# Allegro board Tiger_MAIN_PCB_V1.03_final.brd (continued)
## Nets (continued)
ISH_GYRO2_IRQ*: R113.2 U1.BB7(GPP_A_20_ISH_GP_2)
ISOLATEB: R315.1 R316.1 U9.26(ISOLATEB)
ISW: R3091.2 U2529.10(ISW)
ITP_PMODE: R719.2 U1.E8(ITP_PMODE)
KBC_FAN_SPEED: C608.2 Q47.3(OUT) R607.2 U22.47(TACH0A/GPD6(3))
L_BKLT_EN: R454.1 R455.1 U1.R12(L_BKLTEN) U27.2(B)
L_BRIGHTNESS: Q76.1(G) R3111.1 R3123.2 U1.R11(L_BKLTCTL)
L_OUT+: CN21.2 R628.2
L_OUT-: CN21.1 R627.2
L_VDD_EN: R440.2 U1.U13(L_VDDEN) U25.3(EN/ENB)
LAN_CLK_REQ*: R1.2 U1.AT10(GPP_B_8_SRCCLKREQB_3) U9.16(CLKREQB)
LAN_CMT: R332.2 U11.21(MCT2)
LAN_CMT1: R334.2 U11.15(MCT4)
LAN_CT: R331.2 U11.24(MCT1)
LAN_CT1: R333.2 U11.18(MCT3)
LAN_N1: C399.1 C400.2 C401.2 C402.1 R331.1 R332.1 R333.1 R334.1
LAN_PCIE_CLK_DN: U1.D40(CLKOUT_SRC_N_3) U9.20(REFCLK_N)
LAN_PCIE_CLK_DP: U1.C40(CLKOUT_SRC_P_3) U9.19(REFCLK_P)
LAN_PLT_RST#: R317.1 U9.25(PERSTB) U10.4(Y)
LAN_RST: R318.2 U1.AD1(GPP_C_20_UART2_RXD)
LAN_TX0N: FIL1.1(UNB) R320.2 U11.22(MX1-)
LAN_TX0P: FIL1.4(GND) R319.2 U11.23(MX1+)
LAN_TX1N: FIL2.1(UNB) R324.2 U11.19(MX2-)
LAN_TX1P: FIL2.4(GND) R322.2 U11.20(MX2+)
LAN_TX2N: FIL3.4(GND) R329.2 U11.16(MX3-)
LAN_TX2P: FIL3.1(UNB) R327.2 U11.17(MX3+)
LAN_TX3N: FIL4.4(GND) R335.2 U11.13(MX4-)
LAN_TX3P: FIL4.1(UNB) R330.2 U11.14(MX4+)
LAN_VDDEN: R142.1 R309.2 U8.3(EN/ENB) U22.124(TMRI1/WUI3/GPC6(3))
LANWAKEB: R313.1 U9.28(LANWAKEB)
LAO1_CLKN: CN35.8 U2526.35(TCK1N)
LAO1_CLKP: CN35.9 U2526.34(TCK1P)
LAO1_DATAN0: CN35.24 U2526.42(TA1N)
LAO1_DATAN1: CN35.2 U2526.40(TB1N)
LAO1_DATAN2: CN35.5 U2526.37(TC1N)
LAO1_DATAN3: CN35.10 U2526.32(TD1N)
LAO1_DATAP0: CN35.23 U2526.41(TA1P)
LAO1_DATAP1: CN35.3 U2526.39(TB1P)
LAO1_DATAP2: CN35.6 U2526.36(TC1P)
LAO1_DATAP3: CN35.11 U2526.31(TD1P)
LAO_CLKN: CN35.30 U2526.47(TCK0N)
LAO_CLKP: CN35.29 U2526.46(TCK0P)
LAO_DATAN0: CN35.39 U2526.54(TA0N)
LAO_DATAN1: CN35.36 U2526.52(TB0N)
LAO_DATAN2: CN35.33 U2526.49(TC0N)
LAO_DATAN3: CN35.27 U2526.44(TD0N)
LAO_DATAP0: CN35.38 U2526.53(TA0P)
LAO_DATAP1: CN35.35 U2526.51(TB0P)
LAO_DATAP2: CN35.32 U2526.48(TC0P)
LAO_DATAP3: CN35.26 U2526.43(TD0P)
LCD_VCC: C491.1 C495.2 C942.2 CN35.13 CN35.14 CN35.15 U25.1(VOUT)
LDO2-CAP: C444.2 U16.39(LDO2-CAP)
LDR: R606.1 U2529.11(LDR)
LED_ON: R453.2 U22.19(L80HLAT/BAO/WUI24/GPE0)
LPC_CLKRUN*: R94.2 U1.AW11(GPP_A_8_CLKRUNB) U22.93(CLKRUN#/WUI16/ID0/GPH0)
LPC_FRAME*: CN16.9 U1.BA12(GPP_A_5_LFRAMEB_ESPI_CSB) U22.6(LFRAME#/GPM5(3))
LPC_LAD[0]: CN16.8 U1.AY13(GPP_A_1_LAD_0_ESPI_IO_0) U22.10(LAD0/GPM0(3))
LPC_LAD[1]: CN16.7 U1.BA13(GPP_A_2_LAD_1_ESPI_IO_1) U22.9(LAD1/GPM1(3))
LPC_LAD[2]: CN16.6 U1.BB13(GPP_A_3_LAD_2_ESPI_IO_2) U22.8(LAD2/GPM2(3))
LPC_LAD[3]: CN16.5 U1.AY12(GPP_A_4_LAD_3_ESPI_IO_3) U22.7(LAD3/GPM3(3))
LPCPD#: R488.2 U22.17(LPCPD#/WUI6/GPE6)
M_B_A0: CN1.144(A0) U1.BA46(DDR1_MA_0_CAB9)
M_B_A1: CN1.133(A1) U1.AY46(DDR1_MA_1_CAB8)
M_B_A2: CN1.132(A2) U1.AY47(DDR1_MA_2_CAB5)
M_B_A3: CN1.131(A3) U1.BB46(DDR1_MA_3)
M_B_A4: CN1.128(A4) U1.BA47(DDR1_MA_4)
M_B_A5: CN1.126(A5) U1.AY48(DDR1_MA_5_CAA0)
M_B_A6: CN1.127(A6) U1.BA48(DDR1_MA_6_CAA2)
M_B_A7: CN1.122(A7) U1.AP48(DDR1_MA_7_CAA4)
M_B_A8: CN1.125(A8) U1.BB48(DDR1_MA_8_CAA3)
M_B_A9: CN1.121(A9) U1.AP50(DDR1_MA_9_CAA1)
M_B_A10: CN1.146(A10_AP) U1.AW46(DDR1_MA_10_CAB7)
M_B_A11: CN1.120(A11) U1.AN48(DDR1_MA_11_CAA7)
M_B_A12: CN1.119(A12) U1.AN50(DDR1_MA_12_CAA6)
M_B_A13: CN1.158(A13) U1.BA43(DDR1_MA_13_CAB0)
M_B_ACT_N: CN1.114(ACT*) U1.AN53(DDR1_MA_15_CAA8_ACT_N)
M_B_BG0: CN1.115(BG0) U1.AP52(DDR1_BA_2_CAA5_BG0)
M_B_BG1: CN1.113(BG1) U1.AN52(DDR1_MA_14_CAA9_BG1)
M_B_BS0: CN1.150(BA0) U1.BB44(DDR1_BA_0_CAB4)
M_B_BS1: CN1.145(BA1) U1.BA44(DDR1_BA_1_CAB6)
M_B_CAS_N: CN1.156(A15_CAS*) U1.AY43(DDR1_CAS_N_CAB1_MA15)
M_B_CB0: CN1.92(CB0_NC) R490.2
M_B_CB1: CN1.91(CB1_NC) R492.2
M_B_CB2: CN1.101(CB2_NC) R493.2
M_B_CB3: CN1.105(CB3_NC) R494.2
M_B_CB4: CN1.88(CB4_NC) R495.2
M_B_CB5: CN1.87(CB5_NC) R496.2
M_B_CB6: CN1.100(CB6_NC) R497.2
M_B_CB7: CN1.104(CB7_NC) R501.2
M_B_CKE<0>: CN1.109(CKE0) U1.AN56(DDR1_CKE_0)
M_B_CKE<1>: CN1.110(CKE1) U1.AP55(DDR1_CKE_1)
M_B_CLK_DDR_DN*<0>: CN1.139(CK0_C) U1.AN45(DDR1_CLK_N_0)
M_B_CLK_DDR_DN*<1>: CN1.140(CK1_C) U1.AN46(DDR1_CLK_N_1)
M_B_CLK_DDR_DP<0>: CN1.137(CK0_T) U1.AP45(DDR1_CLK_P_0)
M_B_CLK_DDR_DP<1>: CN1.138(CK1_T) U1.AP46(DDR1_CLK_P_1)
M_B_CS*<0>: CN1.149(S0*) U1.BB42(DDR1_CS_N_0)
M_B_CS*<1>: CN1.157(S1*) U1.AY42(DDR1_CS_N_1)
M_B_DQ<0>: CN1.8(DQ0) U1.AY39(DDRDQ_IL04_NIL10_0)
M_B_DQ<1>: CN1.7(DQ1) U1.AW39(DDRDQ_IL04_NIL10_1)
M_B_DQ<2>: CN1.21(DQ3) U1.AY37(DDRDQ_IL04_NIL10_2)
M_B_DQ<3>: CN1.17(DQ7) U1.AW37(DDRDQ_IL04_NIL10_3)
M_B_DQ<4>: CN1.3(DQ5) U1.BB39(DDRDQ_IL04_NIL10_4)
M_B_DQ<5>: CN1.4(DQ4) U1.BA39(DDRDQ_IL04_NIL10_5)
M_B_DQ<6>: CN1.16(DQ6) U1.BA37(DDRDQ_IL04_NIL10_6)
M_B_DQ<7>: CN1.20(DQ2) U1.BB37(DDRDQ_IL04_NIL10_7)
M_B_DQ<8>: CN1.25(DQ13) U1.AY35(DDRDQ_IL05_NIL11_0)
M_B_DQ<9>: CN1.29(DQ9) U1.AW35(DDRDQ_IL05_NIL11_1)
M_B_DQ<10>: CN1.37(DQ15) U1.AY33(DDRDQ_IL05_NIL11_2)
M_B_DQ<11>: CN1.41(DQ10) U1.AW33(DDRDQ_IL05_NIL11_3)
M_B_DQ<12>: CN1.24(DQ12) U1.BB35(DDRDQ_IL05_NIL11_4)
M_B_DQ<13>: CN1.28(DQ8) U1.BA35(DDRDQ_IL05_NIL11_5)
M_B_DQ<14>: CN1.42(DQ11) U1.BA33(DDRDQ_IL05_NIL11_6)
M_B_DQ<15>: CN1.38(DQ14) U1.BB33(DDRDQ_IL05_NIL11_7)
M_B_DQ<16>: CN1.174(DQ32) U1.AU40(DDRDQ_IL14_NIL12_0)
M_B_DQ<17>: CN1.173(DQ33) U1.AT40(DDRDQ_IL14_NIL12_1)
M_B_DQ<18>: CN1.182(DQ39) U1.AT37(DDRDQ_IL14_NIL12_2)
M_B_DQ<19>: CN1.186(DQ35) U1.AU37(DDRDQ_IL14_NIL12_3)
M_B_DQ<20>: CN1.169(DQ37) U1.AR40(DDRDQ_IL14_NIL12_4)
M_B_DQ<21>: CN1.170(DQ36) U1.AP40(DDRDQ_IL14_NIL12_5)
M_B_DQ<22>: CN1.187(DQ34) U1.AP37(DDRDQ_IL14_NIL12_6)
M_B_DQ<23>: CN1.183(DQ38) U1.AR37(DDRDQ_IL14_NIL12_7)
M_B_DQ<24>: CN1.191(DQ44) U1.AT33(DDRDQ_IL15_NIL13_0)
M_B_DQ<25>: CN1.195(DQ40) U1.AU33(DDRDQ_IL15_NIL13_1)
M_B_DQ<26>: CN1.208(DQ43) U1.AU30(DDRDQ_IL15_NIL13_2)
M_B_DQ<27>: CN1.204(DQ47) U1.AT30(DDRDQ_IL15_NIL13_3)
M_B_DQ<28>: CN1.190(DQ45) U1.AR33(DDRDQ_IL15_NIL13_4)
M_B_DQ<29>: CN1.194(DQ41) U1.AP33(DDRDQ_IL15_NIL13_5)
M_B_DQ<30>: CN1.203(DQ46) U1.AR30(DDRDQ_IL15_NIL13_6)
M_B_DQ<31>: CN1.207(DQ42) U1.AP30(DDRDQ_IL15_NIL13_7)
M_B_DQ<32>: CN1.46(DQ20) U1.AY31(DDRDQ_IL06_NIL14_0)
M_B_DQ<33>: CN1.49(DQ17) U1.AW31(DDRDQ_IL06_NIL14_1)
M_B_DQ<34>: CN1.63(DQ19) U1.AY29(DDRDQ_IL06_NIL14_2)
M_B_DQ<35>: CN1.59(DQ23) U1.AW29(DDRDQ_IL06_NIL14_3)
M_B_DQ<36>: CN1.45(DQ21) U1.BB31(DDRDQ_IL06_NIL14_4)
M_B_DQ<37>: CN1.50(DQ16) U1.BA31(DDRDQ_IL06_NIL14_5)
M_B_DQ<38>: CN1.62(DQ18) U1.BA29(DDRDQ_IL06_NIL14_6)
M_B_DQ<39>: CN1.58(DQ22) U1.BB29(DDRDQ_IL06_NIL14_7)
M_B_DQ<40>: CN1.67(DQ29) U1.AY27(DDRDQ_IL07_NIL15_0)
M_B_DQ<41>: CN1.71(DQ25) U1.AW27(DDRDQ_IL07_NIL15_1)
M_B_DQ<42>: CN1.83(DQ26) U1.AY25(DDRDQ_IL07_NIL15_2)
M_B_DQ<43>: CN1.79(DQ30) U1.AW25(DDRDQ_IL07_NIL15_3)
M_B_DQ<44>: CN1.66(DQ28) U1.BB27(DDRDQ_IL07_NIL15_4)
M_B_DQ<45>: CN1.70(DQ24) U1.BA27(DDRDQ_IL07_NIL15_5)
M_B_DQ<46>: CN1.84(DQ27) U1.BA25(DDRDQ_IL07_NIL15_6)
M_B_DQ<47>: CN1.80(DQ31) U1.BB25(DDRDQ_IL07_NIL15_7)
M_B_DQ<48>: CN1.216(DQ48) U1.AU27(DDRDQ_IL16_NIL16_0)
M_B_DQ<49>: CN1.212(DQ53) U1.AT27(DDRDQ_IL16_NIL16_1)
M_B_DQ<50>: CN1.229(DQ51) U1.AT25(DDRDQ_IL16_NIL16_2)
M_B_DQ<51>: CN1.225(DQ55) U1.AU25(DDRDQ_IL16_NIL16_3)
M_B_DQ<52>: CN1.215(DQ49) U1.AP27(DDRDQ_IL16_NIL16_4)
M_B_DQ<53>: CN1.211(DQ52) U1.AN27(DDRDQ_IL16_NIL16_5)
M_B_DQ<54>: CN1.228(DQ50) U1.AN25(DDRDQ_IL16_NIL16_6)
M_B_DQ<55>: CN1.224(DQ54) U1.AP25(DDRDQ_IL16_NIL16_7)
M_B_DQ<56>: CN1.233(DQ61) U1.AT22(DDRDQ_IL17_NIL17_0)
M_B_DQ<57>: CN1.237(DQ56) U1.AU22(DDRDQ_IL17_NIL17_1)
M_B_DQ<58>: CN1.250(DQ59) U1.AU21(DDRDQ_IL17_NIL17_2)
M_B_DQ<59>: CN1.246(DQ63) U1.AT21(DDRDQ_IL17_NIL17_3)
M_B_DQ<60>: CN1.236(DQ57) U1.AN22(DDRDQ_IL17_NIL17_4)
M_B_DQ<61>: CN1.232(DQ60) U1.AP22(DDRDQ_IL17_NIL17_5)
M_B_DQ<62>: CN1.245(DQ62) U1.AP21(DDRDQ_IL17_NIL17_6)
M_B_DQ<63>: CN1.249(DQ58) U1.AN21(DDRDQ_IL17_NIL17_7)
M_B_DQS_DN*<0>: CN1.11(DQS0_C) U1.BA38(DDRDQSN_IL04_NIL10)
M_B_DQS_DN*<1>: CN1.32(DQS1_C) U1.AY34(DDRDQSN_IL05_NIL11)
M_B_DQS_DN*<2>: CN1.177(DQS4_C) U1.AT38(DDRDQSN_IL14_NIL12)
M_B_DQS_DN*<3>: CN1.198(DQS5_C) U1.AT32(DDRDQSN_IL15_NIL13)
M_B_DQS_DN*<4>: CN1.53(DQS2_C) U1.BA30(DDRDQSN_IL06_NIL14)
M_B_DQS_DN*<5>: CN1.74(DQS3_C) U1.AY26(DDRDQSN_IL07_NIL15)
M_B_DQS_DN*<6>: CN1.219(DQS6_C) U1.AR25(DDRDQSN_IL16_NIL16)
M_B_DQS_DN*<7>: CN1.240(DQS7_C) U1.AR22(DDRDQSN_IL17_NIL17)
M_B_DQS_DP<0>: CN1.13(DQS0_T) U1.AY38(DDRDQSP_IL04_NIL10)
M_B_DQS_DP<1>: CN1.34(DQS1_T) U1.BA34(DDRDQSP_IL05_NIL11)
M_B_DQS_DP<2>: CN1.179(DQS4_T) U1.AR38(DDRDQSP_IL14_NIL12)
M_B_DQS_DP<3>: CN1.200(DQS5_T) U1.AR32(DDRDQSP_IL15_NIL13)
M_B_DQS_DP<4>: CN1.55(DQS2_T) U1.AY30(DDRDQSP_IL06_NIL14)
M_B_DQS_DP<5>: CN1.76(DQS3_T) U1.BA26(DDRDQSP_IL07_NIL15)
M_B_DQS_DP<6>: CN1.221(DQS6_T) U1.AR27(DDRDQSP_IL16_NIL16)
M_B_DQS_DP<7>: CN1.242(DQS7_T) U1.AR21(DDRDQSP_IL17_NIL17)
M_B_ODT<0>: CN1.155(ODT0) U1.BA42(DDR1_ODT_0)
M_B_ODT<1>: CN1.161(ODT1) U1.AW42(DDR1_ODT_1)
M_B_RAS_N: CN1.152(A16_RAS*) U1.AW44(DDR1_RAS_N_CAB3_MA16)
M_B_WE_N: CN1.151(A14_WE*) U1.AY44(DDR1_WE_N_CAB2_MA14)
MDI0+: U9.1(MDIP0) U11.2(TD1+)
MDI0-: U9.2(MDIN0) U11.3(TD1-)
MDI1+: U9.4(MDIP1) U11.5(TD2+)
MDI1-: U9.5(MDIN1) U11.6(TD2-)
MDI2+: U9.7(MDIP2(NC)) U11.8(TD3+)
MDI2-: U9.8(MDIN2(NC)) U11.9(TD3-)
MDI3+: U9.10(MDIP3(NC)) U11.11(TD4+)
MDI3-: U9.11(MDIN3(NC)) U11.12(TD4-)
ME_FLASH: R400.2 R795.2 U22.89(PS2CLK2/WUI20/GPF4)
MIC1L-VREFO: R355.2 U16.31(MIC1-VREFO-L)
MIC1R-VREFO: R356.2 U16.30(MIC1-VREFO-R)
MIC2-VREFO: R3119.1 U16.29(MIC2-VREFO)
MIC_SEL_DET: J2.6 Q36.1(G) R104.1 R359.1
MIC_SEL_SPDIF: Q36.3(D) R346.2 R3122.1 U16.48(SPDIF-OUT/GPIO2)
MPHY_EXT_PWR_GATE*: R54.2 U1.AM10(GPP_B_11_EXT_PWR_GATEB)
NOA_RCOMP: R130.1 U1.E60(NOA_RCOMP)
OVERT: R506.1 U22.119(CRX0/GPC0)
OVPA: R645.2 R883.2 R3096.2 R3113.1 U2529.7(OVP)
PCH_EDM: R718.2 U1.AY3(PCH_EDM)
PCH_LPC_CLK1: CN16.10 U1.AY9(GPP_A_10_CLKOUT_LPC_1)
PCH_PLT_RST*: U1.AN10(GPP_B_13_PLTRSTB) U2.1(A) U2.2(B)
PCH_POPIRCOMP: R42.1 U1.AU16(PCH_POPIRCOMP)
PCH_PWROK: R16.2 R417.2 U1.BA20(PCH_PWROK) U103.39(VR_READY)
PCH_SLP_LAN*: TP10.1 U1.AW15(SLP_LANB)
PCH_SLP_S5*: TP8.1 U1.AY16(GPD_10_SLP_S5B)
PCH_SLP_SA*: TP12.1 U1.AN16(GPD_6_SLP_AB)
PCH_SLP_WLAN*: TP11.1 U1.BB17(GPD_9_SLP_WLANB)
PCH_SUSACK*: R21.2 R25.1 R554.2 R555.1 U1.AP11(GPP_A_15_SUSACKB)
PCH_SUSACK_R*: R554.1 U22.68(ADC2/GPI2(3))
PCH_SUSPWRACK*: R25.2 U1.AR13(GPP_A_13_SUSWARNB_SUSPWRDNACK)
PCH_SYSRST*: R14.2 R413.2 R633.1
PCIE_RCOMPN: R67.2 U1.F5(PCIE_RCOMPN)
PCIE_RCOMPP: R67.1 U1.E5(PCIE_RCOMPP)
PCIE_RST: U1.AB11(GPP_G_0_SD_CMD) U18.2(B)
PCIE_RX_DN*<4>: C394.1 U1.G18(PCIE_6_RXN)
PCIE_RX_DN_1_WIFI: CN26.43(PERN0) U1.F16(PCIE_5_LAN_0C_RXN)
PCIE_RX_DN_9_SSD: CN5.5(PERN3) U1.E22(PCIE_9_LAN_0D_RXN)
PCIE_RX_DN_10_SSD: CN5.17(PERN2) U1.F25(PCIE_10_LAN_0E_RXN)
PCIE_RX_DN_11_SSD: CN5.29(PERN1) U1.E28(PCIE_11_SATA_1B_RXN)
PCIE_RX_DN_12_SSD: R198.1 U1.E30(PCIE_12_SATA_2_RXN)
PCIE_RX_DP<4>: C395.1 U1.F18(PCIE_6_RXP)
PCIE_RX_DP_1_WIFI: CN26.41(PERP0) U1.E16(PCIE_5_LAN_0C_RXP)
PCIE_RX_DP_9_SSD: CN5.7(PERP3) U1.E23(PCIE_9_LAN_0D_RXP)
PCIE_RX_DP_10_SSD: CN5.19(PERP2) U1.E25(PCIE_10_LAN_0E_RXP)
PCIE_RX_DP_11_SSD: CN5.31(PERP1) U1.E27(PCIE_11_SATA_1B_RXP)
PCIE_RX_DP_12_SSD: R197.1 U1.F30(PCIE_12_SATA_2_RXP)
PCIE_TX_C_DN*<4>: C11.1 U1.D20(PCIE_6_TXN)
PCIE_TX_C_DN_1_WIFI: C9.1 U1.C19(PCIE_5_LAN_0C_TXN)
PCIE_TX_C_DP<4>: C12.1 U1.C20(PCIE_6_TXP)
PCIE_TX_C_DP_1_WIFI: C10.1 U1.D19(PCIE_5_LAN_0C_TXP)
PCIE_TX_DN*<4>: C11.2 U9.18(HSIN)
PCIE_TX_DN_1_WIFI: C9.2 CN26.37(PETN0)
PCIE_TX_DN_9_SSD: C322.2 CN5.11(PETN3)
PCIE_TX_DN_10_SSD: C327.2 CN5.23(PETN2)
PCIE_TX_DN_11_SSD: C331.2 CN5.35(PETN1)
PCIE_TX_DN_12_SSD: C333.2 U1.A25(PCIE_12_SATA_2_TXN)
PCIE_TX_DP<4>: C12.2 U9.17(HSIP)
PCIE_TX_DP_1_WIFI: C10.2 CN26.35(PETP0)
PCIE_TX_DP_9_SSD: C326.2 CN5.13(PETP3)
PCIE_TX_DP_10_SSD: C330.2 CN5.25(PETP2)
PCIE_TX_DP_11_SSD: C332.2 CN5.37(PETP1)
PCIE_TX_DP_12_SSD: C338.2 U1.B25(PCIE_12_SATA_2_TXP)
PCIE_WAKE#: R18.2 R313.2 R416.2 R3126.1 R3128.1 U1.BB15(WAKEB)
PD#: U16.47(PDB) U17.4(Y)
PLT_RST_BUF*: CN16.4 R13.1 R155.2 R200.1 R317.2 R401.2 U2.4(Y) U10.1(A) U18.1(A)
PM_BATLOW#: R11.2 U1.AU13(GPD_0_BATLOWB) U22.20(L80LLAT/WUI7/GPE7)
PM_CPUPWRGD: TP5.1 U1.A68(CPUPWRGD)
PM_EC_PWRBTN#: R24.2 U22.97(WUI40/ID4/GPH4)
PM_LANPHY_ENABLE: TP14.1 U1.AW17(GPD_11_LANPHYPC)
PM_RSMRST#: R26.1 U1.AY17(RSMRSTB) U22.112(RING#/PWRFAIL#/CK32KOUT/LPCRST#)
PM_SLP_S0*: R662.1 TP3.1 U1.AT11(GPP_B_12_SLP_S0B) U22.108(RXD/SIN0/GPB0)
PM_SLP_S3*: Q65.1(G) R550.2 R808.1 R828.1 TP4.1 U1.AP15(GPD_4_SLP_S3B) U6.2(B) U22.70(ADC4/WUI28/GPI4(3)) U59.3(ON)
PM_SLP_S4*: Q62.1(G) R552.1 R827.1 TP6.1 U1.BA16(GPD_5_SLP_S4B) U22.69(ADC3/GPI3(3))
PM_SLP_SUS*: Q4.1(G) R71.2 R616.2 U22.56(KSO16/SMOSI/GPC3(3))
PM_SUS_STAT*: R488.1 U1.BA11(GPP_A_14_SUS_STATB_ESPI_RESETB)
PMON_PSYS: C720.1 R218.2 R232.2 R238.2 U103.1(PSYS)
POWER_TP_ON: R382.1 U1.AM11(GPP_B_2_VRALERTB)
POWSW#: D17.N D29.N R791.1 SW1.1
PROCHOT#_EC: R407.2 R426.2 U22.76(TACH2/GPJ0(3)) U23.2(A)
PS_LATCH#: D17.P Q56.1(G) Q57.3(D) R792.2
PS_S3CNTRL: Q21.1(G) Q45.1(G) Q46.3(D) R463.2 R809.2
PSMS: R3009.1 U95.20(GPIO0)
PWM: R528.1 R3106.1 R3109.2 R3110.1 U2529.16(PWM)
PWR_LED: Q49.1(IN) U22.80(DAC4/DCD0#/GPJ4(3))
PWR_SW: C2781.1 CN37.4(VDD) U95.24(PMOS)
PWRONLATCHG: C784.1 C785.2 Q58.4(G) R788.1 R792.1
R_OUT+: CN14.2 R630.2
R_OUT-: CN14.1 R629.2
REGOUT: L3.1 U9.36(REGOUT)
REXT: R2986.2 U2526.26(REXT)
RLV_AMP: R2987.2 U2526.27(RLV_AMP)
RLV_CFG: R2993.1 R2994.2 U2526.22(RLV_CFG)
RLV_LNK: R2996.1 U2525.7(WP/WC#) U2526.21(RLV_LNK/GPIO0)
ROP_SYS_PWROK: R15.2 U1.B6(SYS_PWROK) U22.35(RTS1#/WUI5/GPE5)
ROP_VCCST_PWRGD: Q74.1(G) R23.2 R830.1 U22.87(PS2CLK1/DTR0#/GPF2)
RSET: R307.2 U9.46(RSET)
RSTZ: C2786.1 R802.2 R3008.2 U95.22(RSTZ)
RTA: R958.2 U2529.8(RT)
RTC_RST*: C3.1 R6.1 U1.AM16(RTESTB)
RTC_X1: C6.1 R5.2 U1.AM18(RTCX1) X2.2(B)
RTC_X2: C5.1 R5.1 U1.AM20(RTCX2) X2.1(A)
S3_DISCHARGE: Q52.1(G) Q53.1(G) Q63.1(G) Q64.1(G) Q65.3(D) Q66.1(G) Q67.1(G) R814.1 R821.2
S4_DISCHARGE: Q61.1(G) Q62.3(D) R812.2 R813.1
SA0_DIM1: CN1.256(SA0) R489.1 R491.1
SA1_DIM1: CN1.260(SA1) R389.1 R436.1
SA_BOOT: R258.1 U54.2(BOOT)
SA_COPM: C312.1 R224.2 U103.24(COMP_C)
SA_CSN: C806.2 R237.1 U103.28(ISUMN_C)
SA_CSP: C311.1 R221.1 R223.1 R260.1 U103.27(ISUMP_C)
SA_FCCM: U54.7(FCCM) U103.29(FCCM_C)
SA_HG_DRV: R183.2 U54.1(UGATE)
SA_LG_DRV: Q73.3 U54.5(LGATE)
SA_PHASE: C740.1 LPM10.2 Q73.5 Q73.6 Q73.7 R260.2 U54.8(PHASE)
SA_PWM: U54.3(PWM) U103.30(PWM_C)
SD_CDZ: CN37.11(CD) U95.21(SD_CDZ)
SD_CLK: CN37.5(CLK) U95.14(SD_CLK)
SD_CMD: CN37.2(CMD) U95.15(SD_CMD)
SD_D0: CN37.7(DATA0) U95.13(SB9)
SD_D1: CN37.8(DATA1) U95.12(SB8)
SD_D2: CN37.9(DATA2) U95.17(SB13)
SD_D3: CN37.1(CD/DAT3) U95.16(SB12)
SD_RCOMP: R74.2 U1.AB7(SD_RCOMP)
SD_WP: CN37.10(WP) U95.10(SB5)
SKL_CNL*: R716.1 U1.C64(SKL_CNL_N)
SLPS3#_CONTROL: Q45.3(D) R806.2 R807.2 R810.2
SM_INTRUDER*: R12.1 U1.AP16(INTRUDERB)
SM_RCOMP_0: R53.2 U1.AR18(DDR_COMP_0)
SM_RCOMP_1: R52.2 U1.AT18(DDR_COMP_1)
SM_RCOMP_2: R51.2 U1.AU18(DDR_COMP_2)
SM_VREF_DQ1: R476.1 R512.2
SMB_CLK: Q2.3(D) R82.2 U1.R7(GPP_C_0_SMBCLK)
SMB_CLK_BT: R388.2 U22.110(SMCLK0/GPB3)
SMB_CLK_S2: CN1.253(SCL) Q2.2(S) R85.1 R3001.2
SMB_DATA: Q3.3(D) R83.2 U1.R8(GPP_C_1_SMBDATA)
SMB_DATA_BT: R393.2 U22.111(SMDAT0/GPB4)
SMB_DATA_S2: CN1.254(SDA) Q3.2(S) R84.1 R3000.2
SMB_L1CLK_PCH: R57.2 R396.1 U1.W3(GPP_C_6_SML1CLK)
SMB_L1DATA_PCH: R58.2 R397.1 U1.V3(GPP_C_7_SML1DATA)
SMBCLK: R326.2 U9.14(SMBCLK(NC))
SMBDATA: R321.1 R323.1 R325.2 U9.15(SMBDATA(NC))
SMC_EXTSMI#: R61.2 R403.1 U1.L6(GPP_E_15_DDSP_HPD_2)
SMC_ONOFF#: D29.P U22.125(PWRSW/GPE4(3))
SMC_RUNTIME_SCI#: R62.2 R410.1 U1.N9(GPP_E_16_DDSP_HPD_3)
SMC_SHUTDOWN#: Q57.1(G) R395.2 R789.2
SMC_WAKE_SCI#: R19.2 R412.1 U1.AM15(GPD_2_LAN_WAKEB)
SOC_CATERR*: R29.2 TP18.1 U1.D63(CATERR_N)
SOC_THRMTRIP*: R28.2 TP20.1 U1.C63(THRMTRIPB)
SPK_L+: R628.1 U16.42(SPK-OUT-L+)
SPK_L-: R627.1 U16.43(SPK-OUT-L-)
SPK_R+: R630.1 U16.45(SPK-OUT-R+)
SPK_R-: R629.1 U16.44(SPK-OUT-R-)
SRTCRST*: C4.1 R7.1 U1.AN18(SRTCRSTB)
SSD_CK_REQ_N: CN5.52(CLKREQ# (I/O)(0/3.3V) OR N/C) R181.1
SSD_CLK_REQ*: R180.2 R181.2 R253.2 U1.AT7(GPP_B_6_SRCCLKREQB_1)
SSD_PCIE_CLK_DN: R187.1 U1.B42(CLKOUT_SRC_N_1)
SSD_PCIE_CLK_DP: R194.1 U1.A42(CLKOUT_SRC_P_1)
SSD_PEDET: R174.2 U1.G4(GPP_E_2_SATAXPCIE_2_SATAGP_2)
SSD_SATA_DEVSLP: R175.1 U1.J1(GPP_E_4_SATA_DEVSLP_0)
SSD_SATA_RXN1: C2840.1 U1.G21(PCIE_8_SATA_1A_RXN)
SSD_SATA_RXP1: C2841.1 U1.F21(PCIE_8_SATA_1A_RXP)
SSD_SATA_TXN1: C2843.1 U1.D21(PCIE_8_SATA_1A_TXN)
SSD_SATA_TXP1: C2842.1 U1.C21(PCIE_8_SATA_1A_TXP)
SSTCMP: R3093.1 U2529.15(SSTCMP)
STATUS: R3112.1 U2529.14(STATUS)
SUS_CK: CN5.68(SUSCLK(32KHZ) (O)(0/3.3V)) R8.2 R3004.2 U1.BA17(GPD_8_SUSCLK)
SW1: C767.2 D23.N L26.2 Q30.5 Q30.6 Q30.7 U71.18(SW1)
SW2: C780.1 D28.N L4.1 Q31.5 Q31.6 Q31.7 U71.8(SW2)
SYNC: R620.2 R799.2 U1.BA22(AZA_SYNC_SSP0_SFRM)
TBCLK: R399.2 U22.85(PS2CLK0/CEC/TMB0/GPF0)
TBDATA: R404.2 U22.86(PS2DAT0/TMB1/GPF1)
TEMP_ALERT#: R458.2 R523.2 U5.6(A\L\E\R\T\)
TLS_CONFIDENTIALITY: R90.1 R91.2 U1.R10(GPP_C_2_SMBALERTB)
TXN0_LVDS: C281.2 U2526.5(DRX0N)
TXN1_LVDS: C2846.2 U2526.8(DRX1N)
TXP0_LVDS: C2850.2 U2526.4(DRX0P)
TXP1_LVDS: C2847.1 U2526.7(DRX1P)
USB2_COMP: R66.2 U1.AB6(USB2_COMP)
USB2_DN*<1>: FIL5.1(UNB) R336.1 U1.AB9(USB2N_1)
USB2_DN*<2>: FIL15.1(UNB) R2981.1 U1.AD6(USB2N_2)
USB2_DN*<3>: CN26.5(USB_D-) U1.AH3(USB2N_3)
USB2_DN*<4>: FIL9.3(DUMMY3) R565.1 U1.AD9(USB2N_4)
USB2_DN*<5>: FIL10.1(UNB) R568.1 U1.AJ1(USB2N_5)
USB2_DN*<7>: U1.AH1(USB2N_7) U95.2(DM)
USB2_DN*<10>: U1.AH7(USB2N_10)
USB2_DP<1>: FIL5.4(GND) R337.1 U1.AB10(USB2P_1)
USB2_DP<2>: FIL15.4(GND) R2980.1 U1.AD7(USB2P_2)
USB2_DP<3>: CN26.3(USB_D+) U1.AJ3(USB2P_3)
USB2_DP<4>: FIL9.2(DUMMY2) R564.1 U1.AD10(USB2P_4)
USB2_DP<5>: FIL10.4(GND) R567.1 U1.AJ2(USB2P_5)
USB2_DP<7>: U1.AH2(USB2P_7) U95.3(DP)
USB2_DP<10>: U1.AH8(USB2P_10)
USB2_OC*<0>: C410.1 R63.2 R339.1 R341.2 U1.A9(GPP_E_9_USB2_OCB_0) U12.3(OCB)
USB2_OC*<1>: R64.2 U1.C9(GPP_E_10_USB2_OCB_1)
USB2_OC*<2>: R65.2 U1.D9(GPP_E_11_USB2_OCB_2)
USB2_OC*<3>: R68.2 U1.B9(GPP_E_12_USB2_OCB_3)
USB3_P1_PWREN: R342.2 U1.AD2(GPP_C_21_UART2_TXD) U12.4(EN)
USB3_PWRON: R558.2 R561.2 R563.2 U38.4(EN) U39.4(EN) U40.4(EN)
USB3_RX_DN*<1>: FIL6.4(GND) R338.1 U1.H8(USB3_1_RXN)
USB3_RX_DN*<2>: FIL16.4(GND) R2983.1 U1.J6(USB3_2_SSIC_1_RXN)
USB3_RX_DP<1>: FIL6.1(UNB) R340.1 U1.G8(USB3_1_RXP)
USB3_RX_DP<2>: FIL16.1(UNB) R2982.1 U1.H6(USB3_2_SSIC_1_RXP)
USB3_TX_DN*<1>: C411.2 U1.C13(USB3_1_TXN)
USB3_TX_DN*<2>: C2762.2 U1.B13(USB3_2_SSIC_1_TXN)
USB3_TX_DP<1>: C412.2 U1.D13(USB3_1_TXP)
USB3_TX_DP<2>: C2763.2 U1.A13(USB3_2_SSIC_1_TXP)
USB_OC1#: C710.1 R559.1 R560.2 U38.3(OCB)
USB_OC2#: C661.1 C713.1 R557.2 R562.2 R569.1 R570.1 U39.3(OCB) U40.3(OCB)
USB_WAKEOUT_INTRUDET*: TP16.1 U1.AT15(GPD_7_USB2_WAKEOUTB)
VCLK: C770.1 C779.1 U71.19(VCLK)
VFB1: R782.2 R784.1 U71.2(VFB1)
VFB2: R776.1 R785.1 U71.4(VFB2)
VREFA: C992.1 R3112.2 U2529.12(VREF)
VREG3: C774.1 R775.1 R780.2 U71.3(VREG3)
VREG5: C773.2 U71.13(VREG5)
WIFI_CLK_REQ*: CN26.53(CLKREQ0*) R2.2 U1.AT8(GPP_B_7_SRCCLKREQB_2)
WIFI_PCIE_CLK_DN: CN26.49(REFCLKN0) U1.D41(CLKOUT_SRC_N_2)
WIFI_PCIE_CLK_DP: CN26.47(REFCLKP0) U1.C41(CLKOUT_SRC_P_2)
WIFI_POWERON: R378.1 U19.3(EN/ENB) U22.18(RI1#/WUI0/GPD0(3))
WIFI_RF_KILL_R*: CN26.56(W_DISABLE1* (O)(0/3.3V)) R3005.1
WIRELESS_ON: R3005.2 U22.33(GINT/CTS0#/GPD5)
WLAN_PCIE_WAKE*: R95.2 R3127.1 U1.AP7(GPP_B_16_GSPI0_CLK)
WLAN_PLT_RST: CN26.52(PERST0*) R155.1 U18.4(Y)
WRST#: C481.2 R408.1 U22.14(WRST#)
XCLK_BIASREF: R4.2 U1.E42(XCLK_BIASREF)
XDP_BPM<2>: TP22.1 U1.B54(MBP_N_2)
XDP_BPM<3>: TP23.1 U1.C56(MBP_N_3)
XTAL1: C372.1 U9.43(CKXTAL1) X3.1
XTAL2: C371.1 U9.44(CKXTAL2) X3.3
XTAL24_IN: C1.1 R3.1 U1.E37(XTAL_IN) X1.3
XTAL24_OUT: C2.1 R3.2 U1.E35(XTAL_OUT) X1.1
N26714753: R9.2 R24.1 U1.BA15(GPD_3_PWRBTNB)
N26714785: R616.1 U1.AN15(SLP_SUSB)
N26722992: R56.1 U1.N7(GPP_E_20_DDPC_CTRLCLK)
N26723031: R55.1 U1.N8(GPP_E_21_DDPC_CTRLDATA)
N26739346: R123.1 U1.G20(VCCFUSEPRG)
N26757648: R707.2 R711.2 U42.7(IO3/HOLD*)
N26757763: R136.2 R709.2 U42.3(IO2/WP*)
N26757791: R138.2 U42.2(DO/IO1)
N26757807: R139.2 U42.5(DI/IO0)
N26757835: R137.2 U42.6(CLK)
N29995527: R75.2 U1.AW5(GPP_B_14_SPKR)
N30351746: R39.2 U1.B56(PCH_JTAG_TCK)
N30351752: R35.1 U1.D59(PCH_JTAG_TDI)
N30351756: R31.1 U1.A56(PCH_JTAG_TDO)
N30351760: R30.1 U1.C59(PCH_JTAG_TMS)
N30351779: R40.2 U1.B61(CPU_JTAG_TCK)
N30351789: R32.1 U1.D60(CPU_JTAG_TDI)
N30351793: R33.1 U1.A61(CPU_JTAG_TDO)
N30351797: R34.1 U1.C60(CPU_JTAG_TMS)
N30351801: U1.B59(CPU_JTAG_TRST_N) U1.C61(PCH_TRSTB)
N30362590: R97.1 U1.AR7(GPP_B_18_GSPI0_MOSI)
N30362783: R98.2 U1.AD11(GPP_F_10_I2C5_SDA_ISH_I2C2_SDA)
N30362785: R99.2 U1.AD12(GPP_F_11_I2C5_SCL_ISH_I2C2_SCL)
N30362889: R101.1 U1.AN5(GPP_B_22_GSPI1_MOSI)
N30418600: TP37.1 U1.AK62(VCCGTU_SENSE)
N30418602: TP38.1 U1.AL61(VSSGTU_SENSE)
N30475256: TP39.1 U1.AM23(VCCIO_SENSE)
N30475258: TP40.1 U1.AM22(VSSIO_SENSE)
N30589381: R662.2 R663.1 U6.1(A)
N30589405: C688.2 U67.6(CT)
N31076332: R69.2 R623.2 U1.AW22(AZA_RSTB_SSP1_SCLK)
N31079742: TP43.1 U1.BB5(PGDMON)
N32032184: R111.2 U1.U6(GPP_C_17_I2C0_SCL)
N32032194: R110.2 U1.U7(GPP_C_16_I2C0_SDA)
N32032416: R107.2 U1.AF12(GPP_F_9_I2C4_SCL)
N32032433: R106.2 U1.AF11(GPP_F_8_I2C4_SDA)
N32034483: R108.2 U1.U8(GPP_C_18_I2C1_SDA)
N32034499: R109.2 U1.U9(GPP_C_19_I2C1_SCL)
N32256786: R3124.1 U1.AW50(DDR0_ALERT_N)
N32703185: R122.2 U1.B63(VIDALERT_N)
N32759666: TP21.1 U1.A65(SKTOCC_N)
N32938866: TP35.1 U1.K32(VCCCOREG0)
N32938875: TP36.1 U1.AK32(VCCCOREG1)
N32946040: R37.2 U1.BA5(GPP_B_3_CPU_GP_2)
N33185602: R827.2 R828.2 U56.3(ON)
N33386131: TP45.1 U1.U2(GPP_D_14_ISH_UART0_TXD_SML0BCLK)
N33386639: R118.1 TP44.1 U1.U1(GP_D13_ISH_UART0_RXD_SML0BDAT)
N33387416: R117.1 U1.N3(GPP_D_6_ISH_I2C0_SCL)
N33387421: R116.1 U1.M4(GPP_D_5_ISH_I2C0_SDA)
N34176799: R36.2 U1.C65(PROCHOT_N)
N34374288: C7.1 R48.2
N34404832: C8.1 R49.2
N34544097: C412.1 FIL7.1(UNB) R344.1
N34544176: CN36.3(D_PLUS) D8.N FIL5.3(DUMMY3) R337.2
N34544206: CN36.9(STDA_SSTX+) FIL7.2(DUMMY2) R344.2 U14.2(D-)
N34544208: CN36.8(STDA_SSTX-) FIL7.3(DUMMY3) R343.2 U14.1(D+)
N34544223: CN36.2(D_MINUS) D7.N FIL5.2(DUMMY2) R336.2
N34544234: CN36.5(STDA_SSRX-) FIL6.3(DUMMY3) R338.2 U13.1(D+)
N34544244: C411.1 FIL7.4(GND) R343.1
N34544271: CN36.6(STDA_SSRX+) FIL6.2(DUMMY2) R340.2 U13.2(D-)
N34559149: C488.1 C489.1 R246.1 R247.1 R429.2 U25.5(VIN)
N34559202: C490.2 R429.1 U25.4(SS)
N34566306: C484.1 R425.1 U22.2(CK32KE/GPJ7(3)) X4.4 X5.2
N34566379: C482.1 R424.2 R425.2 U22.128(CK32K/GPJ6(3)) X4.1 X5.1
N34566418: R416.1 U22.21(RI2#/WUI1/GPD1)
N34566506: R409.1 U22.90(PS2DAT2/WUI21/GPF5)
N34566519: R420.2 R421.1 U22.100(SSCE0#/GPG2)
N34566620: R422.2 R423.1 U22.106(SSCE1#/FSCE1#/GPG0)
N34566783: R401.1 U22.22(LPCRST#/WUI4/GPD2)
N34566823: R428.1 U24.3(WP#/ACC)
N34566839: R427.1 U24.7(HOLD#)
N34566853: C483.1 U22.12(VCORE)
N34567017: R410.2 U22.23(ECSCI#/GPD3)
N34567313: R398.1 U22.11(VCC)
N34567537: R403.2 U22.15(ECSMI#/GPD4(3))
N34567565: R412.2 R457.1 U22.16(PWUREQ#/BBO/SMCLK2ALT/GPC7(3))
N34567590: R395.1 U22.82(EGAD/WUI25/GPE1)
N34568048: R413.1 U22.123(CTX0/TMA0/GPB2(3))
N34568559: R417.1 U22.107(DTR1#/SBUSY/GPG1/ID7)
N34568586: R238.1 R466.1 U22.31(PWM5/GPA5)
N34568810: R236.1 U22.66(ADC0/GPI0(3))
N34595104: C398.2 U11.1(TCT1) U11.4(TCT2) U11.7(TCT3) U11.10(TCT4)
N34595477: CN10.7(P7) FIL4.2(DUMMY2) R330.1
N34595569: CN10.5(P5) FIL3.3(DUMMY3) R329.1
N34595612: R318.1 U10.2(B)
N34595656: CN10.6(P6) FIL2.2(DUMMY2) R324.1
N34595663: CN10.1(P1) FIL1.3(DUMMY3) R319.1
N34595676: CN10.2(P2) FIL1.2(DUMMY2) R320.1
N34595746: CN10.3(P3) FIL2.3(DUMMY3) R322.1
N34595869: CN10.4(P4) FIL3.2(DUMMY2) R327.1
N34595884: CN10.8(P8) FIL4.3(DUMMY3) R335.1
N34596140: C374.2 R306.1 U8.4(SS)
N34600101: R362.1 U16.8(SDA TA-IN)
N34600137: C451.1 C452.2 FB13.2 U16.1(DVDD)
N34600193: C453.2 U16.7(LDO3-CAP)
N34600290: C445.2 U16.19(MIC1-L(PORT-B-L))
N34600339: C445.1 R3121.1
N34600341: C446.1 R3120.1
N34600347: C446.2 U16.20(MIC1-R(PORT-B-R))
N34600376: R358.2 R359.2 U16.13(SENSE A)
N34600535: Q19.3(D) R370.2 R372.2 U17.2(B)
N34600597: Q20.1(G) R373.1
N34600740: R357.1 U16.15(JDREF)
N34600742: C443.1 U16.37(CBP)
N34600772: C433.1 U16.34(CPVEE)
N34600774: C443.2 U16.35(CBN)
N34600885: C436.1 U16.27(LDO1-CAP)
N34601042: R349.2 U16.33(HPOUT-R(PORT-I-R))
N34601047: R350.2 U16.32(HPOUT-L(PORT-I-L))
N34601410: Q19.1(G) Q20.3(D) R371.2
N34603029: C470.2 R377.1 U19.4(SS)
N34621634: Q49.3(OUT) R611.2
N34621650: LED2.2(N) R611.1
N34623411: D18.N Q47.1(IN)
N34623413: C610.1 R609.1
N34852317: R621.2 U1.AY22(AZA_BCLK_SSP0_SCLK)
N34852593: Q51.2(S) R624.2 R626.2
N34852599: Q51.1(G) R625.1
N34856886: R633.2 U1.B5(SYS_RESETB)
N34946454: C802.2 Q4.3(D) Q68.4(G) R70.2
N35241025: Q55.8 R765.2
N35241085: Q55.3 R768.2
N35241097: R392.1 U41.2(TON)
N35241124: R762.1 U41.11(TRIP)
N35241153: C761.2 R763.1 U41.4(V5FILT)
N35249184: R786.2 U71.15(DRVL1)
N35249190: R787.2 U71.16(DRVH1)
N35249200: C767.1 U71.17(VBST1)
N35249223: C780.2 U71.9(VBST2)
N35249239: C779.2 D25.3(D3)
N35249270: C781.1 D24.2(X2) D25.1(X1)
N35249299: R780.1 U71.20(EN1)
N35249362: R775.2 U71.6(EN2)
N35249370: R72.2 U71.7(PGOOD)
N35249515: R781.1 U71.11(DRVL2)
N35249639: R783.1 U71.10(DRVH2)
N35249877: R778.2 U71.1(CS1)
N35250139: C770.2 D24.3(D3)
N35250147: R779.1 U71.5(CS2)
N35254494: Q59.1(G) R795.1
N35254509: Q59.3(D) R796.2
N35255522: C563.1 R801.1 U35.5(VIN1) U35.E1(VIN2)
N35256124: R771.1 R773.2 U70.6(FB)
N35256155: C341.1 C343.1 R770.2 R772.1 R800.1 U70.8(VDD) U70.9(PVDD2) U70.10(PVDD1)
N35256187: R770.1 R825.1 U70.7(NC1)
N35256211: L25.1 U70.2(LX1) U70.3(LX2)
N35256295: R772.2 U70.5(EN)
N35277788: C795.2 Q60.4(G) R807.1
N35277870: C790.2 Q43.4(G) R810.1
N35277915: Q46.1(G) R808.2
N35278836: Q61.3(D) R811.1
N35279533: Q63.3(D) R817.1
N35279539: Q64.3(D) R818.1
N35279545: Q52.3(D) R820.1
N35279549: Q67.3(D) R819.1
N35279555: Q66.3(D) R815.1
N35279596: Q53.3(D) R816.1
N35557452: D31.P R182.1
N35572372: C344.2 D26.N R391.2
N35765595: R102.1 U22.79(DAC3/TACH1B/GPJ3(3))
N35765799: R104.2 U22.72(ADC6/DSR1#/WUI30/GPI6(3))
N35765995: R112.1 U1.AB1(GPP_C_8_UART0_RXD)
N35766000: R105.1 U1.AB2(GPP_C_9_UART0_TXD)
N35767454: R38.2 U1.A7(GPP_E_7_CPU_GP_1)
N35770734: R134.2 U1.W4(GPP_C_10_UART0_RTSB)
N35770739: R77.2 U1.AB3(GPP_C_11_UART0_CTSB)
N35788104: R140.1 U1.L12(GPP_E_19_DDPB_CTRLDATA)
N35805724: R142.2 U1.AP8(GPP_B_17_GSPI0_MISO)
N36034869: C14.1 C735.1 C736.1 C737.1 FB26.2 Q73.1 Q73.2
N36034873: C730.1 C731.1 C732.1 C733.1 C734.1 CP10.1 FB24.1 FB25.1 Q71.5(D1) Q71.6(D2) Q71.7(D3) Q71.8(D4)
N36034997: C740.2 R258.2
N36035123: Q73.8 R183.1
N36035170: C308.2 R669.1 U103.2(IMON_B)
N36035178: C324.2 C717.1 R208.2 R591.1 R667.2
N36035212: C723.1 C724.1 C725.1 C727.1 C728.1 C2853.1 C2854.1 CP51.1 CP52.1 FB22.1 FB23.1 Q69.5(D1) Q69.6(D2) Q69.7(D3) Q69.8(D4)
N36035226: C722.1 R220.2 U103.16(COMP_A)
N36035247: C303.1 R216.1
N36035348: C305.2 C719.2 R222.1 R681.1 R683.1
N36035428: C316.1 R680.2 U103.14(IMON_A)
N36035485: Q69.4(G) R689.2
N36035580: R216.2 R217.2 U103.20(ISUMN_A)
N36035694: R678.2 U103.15(NTC_A)
N36035696: R229.2 R678.1
N36035835: R213.1 R215.2
N36035841: R671.1 U103.3(NTC_B)
N36035843: R219.1 R671.2
N36035870: R234.2 U103.32(PROG1)
N36036104: C721.1 R239.1
N36036129: R235.2 U103.31(PROG2)
N36036375: C314.1 R226.1
N36036466: C719.1 R227.1
N36036545: C309.1 R220.1
N36036623: R208.1 R209.1 R210.1 U103.5(FB_B)
N36036629: C302.2 R210.2
N36036665: C299.2 R244.2
N36036687: C306.2 R590.2 R668.2 U103.6(RTN_B)
N36036762: C294.2 R168.2
N36036804: R205.1 R206.2
N36036974: C300.2 R211.1 U103.4(COMP_B)
N36037016: C301.2 R211.2
N36037139: C717.2 R209.2
N36037141: C318.1 R230.1 R672.1 R674.2
N36037149: C318.2 R231.1
N36037438: C313.1 R224.1
N36037621: C295.2 R212.1 U103.8(ISUMN_B)
N36037625: C295.1 R207.1
N36037871: C738.2 R249.2
N36037926: C806.1 R228.2
N36059207: Q56.3(D) R794.1
N36084711: C700.2 U59.6(CT)
N36086308: C808.2 U56.6(CT)
N36091446: R534.1 R536.2 U35.2(FB)
N36093005: R535.1 U35.8(EN)
N36133789: Q1.1(G) Q74.3(D) R829.2
N36535071: R255.2 U1.AM5(GPP_B_19_GSPI1_CSB)
N36535773: R255.1 R264.1
N36703241: CN1.166(SA2) R386.1 R435.1
N36703730: CN1.134(EVENT*) R385.2
N36791597: C274.2 R512.1 U1.BA67(DDR_VREF_DQ_1)
N36791664: C274.1 R513.2
N36887704: Q26.1(B) Q26.3(C) R521.2
N36887763: C669.2 R522.1 U5.3(DN)
N36887773: Q26.2(E) R522.2
N36887775: C669.1 R521.1 U5.2(DP)
N36901448: R458.1 R462.1 U22.104(DSR0#/GPG6)
N36968587: Q71.4(G) R254.2
N36968684: Q72.4(G) R256.2
N36971587: R464.1 R469.2 U21.2(FB)
N36971603: C511.1 R468.1 U21.5(VIN1) U21.E1(VIN2)
N36971629: R270.1 R470.1 U21.8(EN)
N36971657: R271.2 U21.7(POK)
N36979254: CN1.97(DQS8_T) R471.1
N36979257: CN1.95(DQS8_C) R472.1
N37048296: R487.1 U22.4(KBRST#/GPB6(3))
N37063122: C697.1 L5.1 U29.17(PHASE1) U29.18(PHASE2) U29.19(PHASE3) U29.20(PHASE4) U29.25(PHASE5) U29.35(PHASE6)
N37063333: R543.1 U29.10(CS)
N37063789: R544.1 R545.1 U29.8(PGOOD)
N37064197: C697.2 U29.27(BOOT)
N37066595: C703.2 U29.1(VTTREF)
N37068393: C704.1 R546.1 R547.1 U29.3(FB)
N37069902: R548.1 R552.2 U29.6(S5)
N37069925: Q21.3(D) R551.2
N37070732: R553.2 U29.7(TON)
N37076872: R419.1 U22.67(ADC1/GPI1(3))
N37309832: CN23.2(D_MINUS) D19.N FIL10.2(DUMMY2) R568.2
N37309834: CN23.3(D_PLUS) D20.N FIL10.3(DUMMY3) R567.2
N37310702: CN22.2(D_MINUS) D21.N FIL9.4(GND) R565.2
N37310717: CN22.3(D_PLUS) D22.N FIL9.1(UNB) R564.2
N37310916: CN24.2(D_MINUS) D2513.N FIL15.2(DUMMY2) R2981.2
N37310918: CN24.5(STDA_SSRX-) FIL16.3(DUMMY3) R2983.2 U2523.1(D+)
N37310933: C2762.1 FIL14.4(GND) R2978.1
N37310942: CN24.6(STDA_SSRX+) FIL16.2(DUMMY2) R2982.2 U2523.2(D-)
N37310944: CN24.9(STDA_SSTX+) FIL14.2(DUMMY2) R2979.2 U2524.2(D-)
N37310966: C2763.1 FIL14.1(UNB) R2979.1
N37310979: CN24.3(D_PLUS) D2512.N FIL15.3(DUMMY3) R2980.2
N37311057: CN24.8(STDA_SSTX-) FIL14.3(DUMMY3) R2978.2 U2524.1(D+)
N37376325: C418.1 J3.4 R366.1
N37376350: C414.1 J2.4 R347.1
N37376400: C413.1 J2.3 R348.1
N37376460: C419.1 J3.3 R365.1
N37412625: R2985.2 R2997.2 U2526.45(PWMI)
N37412638: R2984.1 U2526.20(TESTMODE)
N37412835: L9.2 U2526.15(SW_OUT) U2526.16(SW_OUT-1)
N37413349: R2988.1 U2527.7(WP/WC#)
N37416123: CN26.58(I2C DATA (IO)(0/3.3)) R3000.1
N37416136: CN26.60(I2C CLK (O)(0/3.3)) R3001.1
N37416331: CN26.50(SSCLK) R3004.1
N37456108: R3098.1 R3102.2
N37456113: R636.2 R3099.1
N37456118: R756.2 R3100.1
N37456123: R755.1 R3101.1
N37456573: Q48.1(G) Q76.3(D) R3108.2
N37456813: Q95.2(S) R3091.1 R3114.2 R3115.2 R3116.2 R3117.2
N37456912: Q95.1(G) R606.2
N37456959: D38.P D42.P L32.2 Q95.3(D) R291.2
N37457475: J5.5 R3118.1
N37457477: J5.6 R3097.1
N37458124: CN3.P7 R748.2
N37458279: C2840.2 CN3.S5
N37458285: C2842.2 CN3.S2
N37458287: C2843.2 CN3.S3
N37458304: C2841.2 CN3.S6
N37481490: R3122.2 U22.109(TXD/SOUT0/GPB1)
N37491665: R452.2 U27.4(Y)
N37619180: R3125.1 U1.AT52(DDR0_PARITY)
N37654536: CN26.55(PEWAKE0*) R3126.2 R3127.2
N37689085: CN5.38(DEVSLP (O)) R175.2
N37689147: CN5.69(PEDET (NC-PCIE/GND-SATA)) R174.1 R199.2 R240.1
N37689278: CN5.53(REFCLKN) R187.2
N37689280: CN5.55(REFCLKP) R194.2
N37689443: CN5.43(PERP0/SATA-B-) R198.2
N37689445: CN5.41(PERN0/SATA-B+) R197.2
N37689471: C338.1 CN5.49(PETP0/SATA-A+)
N37689473: C333.1 CN5.47(PETN0/SATA-A-)
N37689619: CN5.50(PERST# (O)(0/3.3V) OR N/C) R200.2
N37690406: C326.1 U1.A23(PCIE_9_LAN_0D_TXP)
N37690408: C322.1 U1.B23(PCIE_9_LAN_0D_TXN)
N37690460: C327.1 U1.D23(PCIE_10_LAN_0E_TXN)
N37690481: C330.1 U1.C23(PCIE_10_LAN_0E_TXP)
N37690514: C331.1 U1.D24(PCIE_11_SATA_1B_TXN)
N37690535: C332.1 U1.C24(PCIE_11_SATA_1B_TXP)
N37690970: CN5.54(PEWAKE# (I/O)(0/3.3V) OR N/C) R3128.2
N37767608: CN9.B D6.N F8.2 R3129.2
N37767624: CN9.D R303.1
N37767652: C461.2 R3129.1
N37767697: F8.1 FB4.2 FB5.2
N37788612: Q70.4(G) R690.2
N37895377: R221.2 R225.2
N37928976: C264.1 R291.1
N360368650: C718.1 R185.1
N374569031: C2834.2 R3093.2
N3524071713: R391.1 U41.14(VBST)

Pads without a net: CN1 162 165; CN3 P1 P2 P3 P11 P13 P14 P15; CN5 6 8 10 20 22 24 26 28 30 32 34 36 40 42 44 46 48 56 58 67; CN16 11 13 20; CN26 6 8 9 10 11 12 13 14 15 16 17 19 20 21 22 25 26 27 28 30 31 32 34 38 40 42 44 46 48 59 61 62 64 65 66 67 68 70 71 73; CN35 16 17 18; MARK1 1; MARK2 1; MARK3 1; MARK4 1; MARK5 1; MARK6 1; MARK7 1; MARK8 1; R2984 2; U1 A3 A4 A6 A11 A15 A17 A19 A21 A26 A27 A29 A31 A33 A36 A38 A40 A45 A47 A50 A52 A59 A69 AB4 AB12 AB62 AC1 AC2 AC3 AC63 AD3 AD4 AE62 AE63 AF6 AF7 AF8 AF9 AF13 AF64 AF65 AF66 AF67 AF68 AF69 AF70 AF71 AG1 AG2 AG3 AG4 AG62 AG69 AG70 AH9 AH10 AH11 AH12 AH65 AH66 AH68 AH69 AH70 AH71 AJ62 AK6 AK7 AK9 AK10 AK12 AK13 AK42 AK43 AK45 AK46 AK48 AK50 AK52 AK53 AK55 AK56 AK58 AK60 AK64 AK65 AK66 AK67 AK70 AL25 AL27 AL43 AL46 AL50 AL53 AL56 AL60 AL63 AL68 AL69 AL70 AL71 AM1 AM2 AM3 AM4 AM48 AM50 AM52 AM53 AM56 AM58 AM69 AM70 AN1 AN2 AN3 AN7 AN8 AN55 AN60 AN61 AN65 AN66 AN68 AN69 AN70 AN71 AP1 AP2 AP3 AP4 AP5 AP13 AP53 AP56 AP60 AP61 AP65 AP66 AR10 AR56 AR60 AR61 AR65 AR66 AR68 AR69 AR70 AR71 AT5 AT43 AT45 AT46 AT48 AT50 AT53 AT55 AT60 AT61 AT65 AT66 AT69 AT70 AU1 AU2 AU5 AU7 AU8 AU43 AU45 AU46 AU48 AU50 AU52 AU53 AU55 AU56 AU58 AU60 AU61 AU63 AU65 AU66 AU68 AU69 AU70 AU71 AW1 AW7 AW20 AW48 AW52 AW54 AW56 AW59 AW61 AW63 AW65 AW68 AW69 AW70 AW71 AY1 AY2 AY4 AY5 AY7 AY20 AY21 AY50 AY51 AY52 AY54 AY55 AY56 AY59 AY60 AY61 AY63 AY64 AY65 B2 B3 B7 B11 B15 B17 B19 B21 B26 B27 B29 B31 B33 B36 B38 B40 B45 B47 B50 B69 B70 BA3 BA4 BA7 BA9 BA50 BA51 BA52 BA54 BA55 BA56 BA59 BA60 BA61 BA63 BA64 BA65 BA68 BA70 BB2 BB3 BB4 BB9 BB11 BB50 BB52 BB54 BB56 BB57 BB59 BB61 BB63 BB65 BB66 BB68 BB69 C2 C4 C7 C8 C11 C12 C15 C16 C17 C27 C28 C29 C31 C32 C33 C36 C37 C38 C42 C50 C51 C52 C54 C55 C67 C70 C71 D1 D3 D4 D5 D7 D8 D12 D15 D16 D17 D27 D28 D29 D31 D32 D33 D36 D37 D38 D42 D50 D51 D52 D54 D55 D56 D61 D71 E1 E2 E3 E10 E20 E38 E40 E43 E48 E55 E58 E61 E63 E66 F6 F10 F11 F15 F20 F43 F46 F48 F50 F52 F53 F55 F56 F58 F60 F61 F63 F65 F66 G1 G2 G3 G11 G13 G15 G16 G46 G50 G53 G56 G61 G65 G68 G70 H1 H2 H3 H5 H10 H11 H13 H16 H63 H69 J2 J3 J4 J5 J10 J68 J71 K45 K46 L7 L9 L13 M1 M2 M3 N1 N2 N11 N12 P1 P2 P3 P4 P62 R9 U3 U4 U11 U12 V1 V2 V62 W2 W7 W8 W10 W11 W12; U4 1; U9 31 37 40; U16 12 14 16 21 22 23 24; U22 29 32 36 37 38 39 40 41 42 43 44 45 46 48 51 52 53 54 55 58 59 60 61 62 63 64 65 73 77 78 81 83 84 88 96 98 99 118; U23 1; U29 26; U70 1; U95 5 6 7 8 9 11; U103 13; U2526 55 56

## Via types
v1: diameter 0.7, hole 0.4, TOP to BOTTOM, 872 vias
v2: diameter 0.45, hole 0.25, TOP to BOTTOM, 2702 vias

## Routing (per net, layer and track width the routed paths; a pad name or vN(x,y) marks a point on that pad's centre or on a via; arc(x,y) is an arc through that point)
+V1.05A_EN: length 146.9
  TOP w0.254: v2(163.24,43.01) 163.24,42.76 163.5,42.5 R769.1 163.98,42.5 ; 163.98,42.5 164.03,42.56 U41.1 ; 163.98,42.5 C804.1
  LAY3 w0.102: v2(50.06,54.52) 49.43,55.14 49.43,66.82 48.89,67.37 48.89,70.89 47.99,71.79 v2(47.99,75.4)
  LAY6 w0.102: v2(50.06,54.52) 50.4,54.86 51.77,54.86 53.13,56.22 75.95,56.22 76.47,55.7 84.74,55.7 85.4,55.04 92.25,55.04 92.98,54.3 96.79,54.3 98.06,53.03 114.52,53.03 118.36,49.2 119.82,49.2 120.38,49.75 124.41,49.75 125.23,48.94 125.56,48.94 126.13,48.37 132.12,48.37 133.23,49.48 139.39,49.48 146.81,42.06 161.32,42.06 162.27,43.01 v2(163.24,43.01)
  BOTTOM w0.102: R462.2 v2(47.99,75.4)
+V1.5S: length 214.4
  TOP w0.305: R534.2 147.73,48.53 R819.2 149.85,48.73 150.17,49.06 150.17,49.92 v1(150.13,49.96) ; v2(157.27,36.28) 149.89,43.66 149.89,47.76 150.75,48.62 150.75,50.24
  TOP w0.508: v2(25.35,32.13) 25.35,36.85 43.58,55.08 44.98,55.08 v2(45.79,55.89)
  LAY6 w0.305: v2(180.03,39.75) 179.91,39.63 178.2,39.63 177.92,39.35 173.46,39.35 172.64,40.18 168.37,40.18 162.91,34.72 158.83,34.72 v2(157.27,36.28)
  LAY6 w0.508: v1(150.13,49.96) 146.98,49.96 144.89,52.05 118.83,52.05 113.84,57.04 100.86,57.04 99.78,58.12 95.76,58.12 95.03,58.86 72.12,58.86 71.05,57.79 65.38,57.79 65.02,58.16 61.09,58.16 59.89,56.96 51.73,56.96 50.67,55.89 v2(45.79,55.89) ; v2(23.79,16.27) 24.34,16.82 24.34,18.58 25.35,19.59 v2(25.35,32.13)
  BOTTOM w0.305: R826.2 180.42,39.36 v2(180.03,39.75)
  BOTTOM w0.406: R361.2 21.84,17.29 C431.2 22.71,16.48 FB10.2
  BOTTOM w0.508: FB10.2 v2(23.79,16.27)
+V1.8U_2.5U_MEM: length 4.5
  BOTTOM w0.305: 187.04,26.91 187.6,27.47 187.6,27.48 ; R464.2 187.11,29.26 187.6,28.76 187.6,27.48 ; 187.6,27.48 188.03,27.05
  vias: v1(172.24,22.35)
+V1P00A: length 258.4
  TOP w0.203: v2(196.28,67.4) 196.28,67.31 U1.Y18 196.6,66.8 U1.AB17 ; v2(185.84,71.95) 185.87,71.97 186.83,71.97 U1.L1 ; U1.A10 191.85,78.08 v2(191.78,78.11) ; v2(198.79,61.42) 198.49,61.6 198.41,61.6 198.28,61.73 U1.AK20 ; U1.T1 185.82,69.3 185.31,69.81 182.9,69.81 v2(182.39,70.31) ; U1.A14 194.33,78.14 v2(194.2,78.27)
  TOP w0.254: U41.3 165.53,44.88 165.91,44.51 165.91,43.92 166.56,43.27 ; v2(194.32,69.92) 194.32,70 U1.N15 ; U1.L19 197.3,71.17 v2(197.58,70.81) ; v2(209.2,82.54) 209.52,82.86 R4.1 ; U1.AF18 v2(196.93,64.05) ; U1.AB20 v2(197.58,65.73) ; U1.L15 v2(194.31,71.6) U1.K15 ; v2(198.88,67.4) U1.V21 ; U1.V21 198.58,67.83 v2(198.88,68.22) ; U1.V21 198.48,67.75 197.98,67.75 U1.V20 ; U1.K17 v2(196.2,71.7) ; U1.N16 195.3,70.39 194.98,70.71 v2(194.98,70.81) ; U1.T20 197.91,68.64 v2(197.58,68.22) 197.25,68.64 U1.T19 197.26,68.64 v2(196.93,68.22) ; U1.AB19 v2(196.93,65.73) ; v2(191.78,78.11) 191.78,79.72 C240.2 ; U1.AF21 v2(198.23,64.89) U1.AF20 ; U1.P16 195.3,69.61 v2(195.62,69.92) 195.62,70 U1.N17 ; U1.AF19 v2(197.58,64.05) ; U1.P18 196.6,69.5 v2(196.28,69.09) ; U1.V15 v2(194.32,68.24) ; v2(196.97,71.7) 197.21,72.01 U1.K19 ; v2(194.97,69.92) 194.65,69.61 U1.P15 ; U1.N20 v2(198.23,69.92) ; U1.N18 v2(196.93,69.93) ; U1.L21 v2(198.23,71.6)
  TOP w0.305: C234.1 181.85,81.45 v2(182.56,80.74) ; C237.1 183.57,80.92 v2(183.58,80.9) ; R816.2 160.67,69.72 ; v2(185.83,80.86) 185.83,81.76 C238.1 185.2,80.92 v2(185.18,80.89) ; v2(184.4,80.88) 184.27,81.02 184.27,82.07 ; v2(181.79,80.78) 181.12,81.45 181.12,82.17 ; 166.56,43.27 v2(168.1,43.27) ; v2(185.84,71.95) 185.76,72.03 C230.2 ; C242.1 180.05,81.7 v2(180.99,80.76) ; R764.2 v2(169.16,47.71)
  TOP w0.508: 168.18,78.27 167.51,78.94 167.51,80.48 169.3,82.27 C685.2 ; v1(174.65,61.47) 174.07,62.06 173.22,62.06 171.1,64.17 170.4,64.17 ; 170.45,68.04 171.02,68.04 171.51,67.55 171.51,66.52 172.1,65.92 174.01,65.92 v1(174.54,65.4) ; 170.45,68.04 170.12,68.37 ; 170.45,68.04 170.45,68.02 170.1,67.68
  LAY3 w0.152: v2(198.79,61.42) 198.39,61.82 193.25,61.82 192.78,62.29 192.12,62.29 191.01,61.18 189.92,61.18 189.45,60.71 187.62,60.71 187.16,61.17
  LAY3 w0.254: v2(197.58,70.81) 198.41,70.81 198.75,71.15 199.81,71.15 200.14,71.48 200.14,72.64 200.36,72.85 210.6,72.85 211.12,73.37 211.12,81.78 210.36,82.54 v2(209.2,82.54) ; v2(194.2,78.27) 194.26,78.27 195.2,77.33 195.2,73.95 195.89,73.26 195.89,72.01 v2(196.2,71.7) ; v2(194.31,71.6) 194.31,72.2 192.85,73.66 192.85,77.04 v2(191.78,78.11) ; v2(176.44,68.19) 176.87,67.76 184.07,67.76 184.88,68.57 193.98,68.57 v2(194.32,68.24) ; v2(177.75,61.72) 178.3,61.17 187.16,61.17 ; v2(196.28,69.09) 196.28,68.19 195.73,67.65 195.73,67.19 196.93,65.99 v2(196.93,65.73)
  BOTTOM w0.254: 173.87,74.43 173.87,75.19 175.22,76.54 175.22,78.03 176.81,79.62 179.88,79.62 182.08,77.42 186.27,77.42 186.83,76.86 194.21,76.86 ; 173.87,74.43 173.55,74.11 ; 173.87,74.43 174.14,74.16
  BOTTOM w0.305: v2(196.93,69.93) 196.86,70 C241.2 ; 171.78,68.1 171.94,68.1 171.94,67.95 173.45,66.44 176.25,66.44 176.88,67.06 C243.1 176.88,67.75 v2(176.44,68.19) ; v2(183.58,80.9) 184.11,80.37 193.9,80.37 195.92,78.35 ; v1(166.21,66.15) 166.21,64.91 164.41,63.11 164.41,54.8 166.39,52.81 166.39,49.97 168.65,47.71 v2(169.16,47.71) ; v2(168.1,43.27) 166.91,44.46 166.91,47.62 165.79,48.74 165.79,52.46 163.72,54.53 163.72,63.22 165.46,64.95 v1(165.46,66.15) ; 194.54,77.38 193.83,77.38 191.76,79.45 183.85,79.45 v2(182.56,80.74)
  vias: v1(165.53,68.82) v1(166.41,68.82) v1(167.63,66.15) v1(167.91,68.77) v1(168.57,66.15) v1(168.75,68.77) v1(170.17,75.33) v1(171.04,75.33) v2(170.57,77.2) v2(171.11,77.2) v2(171.71,77.2) v2(179.69,61.72) v2(180.32,61.72)
+V1P00A_FB: length 3.3
  TOP w0.254: U41.5 166.29,45.88 R766.2 R764.1
+V1P00S_VCCST: length 103.2
  TOP w0.203: U1.A18 196.81,77.56 195.92,78.46 v2(195.92,79.18) ; R20.1 231.03,83.39 R716.2 231.03,83.12 R124.1 ; R125.1 229.28,82.16 R124.1 ; R124.1 230.24,83.12 v2(229.76,83.59) 228.43,84.93 R28.1 R29.1
  TOP w0.254: U1.K20 197.97,72.02 198.03,72.08 198.43,72.08 198.49,72.01 U1.K21 v2(198.88,71.6) ; C208.2 195.92,79.18 v2(195.92,79.18)
  TOP w0.406: 174.62,82.19 175.28,82.19 175.95,82.86 176.65,82.86 177.76,83.97 C687.2 178.74,83.36 v2(178.74,83.35)
  LAY3 w0.254: v2(195.92,79.18) 196.11,78.99 196.11,75.72 196.51,75.32 196.51,72.71 197.06,72.16 198.32,72.16 v2(198.88,71.6) 199.22,71.93 199.22,72.35 200.07,73.2 207.24,73.2 207.49,73.45 207.49,82.19 208.94,83.65 217.08,83.65 219.3,81.43 219.3,80.08 220.19,79.19 222.24,79.19 223.27,80.22 223.27,81.82 225.35,83.9 229.45,83.9 v2(229.76,83.59)
  BOTTOM w0.203: v2(229.76,83.59) 229.76,83.06 230.55,82.28 231.01,82.28 231.4,81.89 231.4,80.91 231.72,80.59 232.89,80.59 R714.1 R713.2 ; C219.2 199.23,71.25 v2(198.88,71.6) 198.68,71.8 C218.2
  BOTTOM w0.254: v2(195.92,79.18) 195.92,79.69 193.77,81.83 188.23,81.83 187.22,80.82 186.63,80.82 185.86,81.59 180.5,81.59 v2(178.74,83.35)
+V1P00S_VCCSTG: length 176.2
  TOP w0.203: U1.AL30 v2(203.36,60.8) ; U1.AL30 v2(203.36,62.36) ; U1.AL30 203.82,61.21 U1.AM30 ; v2(222.23,82.71) 222.27,82.66 R59.2 224.33,83.26 R34.2 223.9,83.69 R32.2 224.28,84.44 225.31,85.47 228.64,85.47 229.24,84.87 232.71,84.87 233.08,84.5 233.08,80.9 R27.1 ; v2(203.36,62.36) 203.59,62.36 U1.AK30 ; v2(203.36,62.36) 203.13,62.36 U1.AK28 ; v2(199.29,78.14) U1.A22 ; U1.AL42 210.23,61.2 U1.AM42 210.61,60.8 v2(210.68,60.8)
  TOP w0.254: v2(199.29,78.14) 199.09,78.14 198.68,78.55 C216.2 ; v2(203.36,60.8) U1.AM28 ; U1.AM30 v2(204.28,60.8)
  LAY3 w0.254: 204.34,87.04 201.42,87.04 199.47,85.09 v2(199.47,84.76) 198.73,84.02 195.28,84.02 194.54,84.76 188.49,84.76 187.44,85.8 182.2,85.8 178.85,89.15 169.19,89.15 166.77,86.72 v2(166.77,84.26) ; 204.34,87.04 204.4,86.97 204.4,80.4 203.65,79.65 203.65,77.8 203.41,77.55 202.13,77.55 201.54,78.14 v2(199.29,78.14) ; 204.34,87.04 207.34,87.04 207.67,87.37 220.04,87.37 221.06,88.38 v2(222.05,88.38) ; v2(157.85,56.23) 157.85,59.32 158.55,60.02 158.55,65.39 157.73,66.21 157.73,67.84 v2(158.69,68.8)
  LAY3 w0.305: v2(210.68,60.8) 210.09,61.38 204.86,61.38 v2(204.28,60.8)
  LAY6 w0.254: v2(222.23,82.71) 221.67,83.27 221.67,88 v2(222.05,88.38)
  LAY6 w0.305: v2(157.85,56.23) 157.87,56.23 158.44,55.66 164.51,55.66 166.78,57.93 170.23,57.93 v1(170.51,57.65)
  BOTTOM w0.254: R33.2 222.73,83.43 222.73,83.21 v2(222.23,82.71) ; C181.1 210.65,60.77 v2(210.68,60.8)
  BOTTOM w0.305: v2(222.23,82.71) 221.76,83.18 221.76,83.4 R31.2 221.24,83.42 R35.2 221.75,82.33 221.75,80.61 220.71,79.57 219.99,79.57 219.63,79.93 R30.2 ; R123.2 198.86,84.03 199.47,84.64 v2(199.47,84.76)
  BOTTOM w0.406: v2(158.69,68.8) 161.41,71.52 161.41,78.25 166.77,83.61 v2(166.77,84.26)
  vias: v1(170.52,56.86) v1(171.25,57.65) v1(171.26,56.86)
+V1P8A: length 46.6
  TOP w0.305: v2(170.67,67.3) 170.67,66.3 172.68,64.29 172.68,63.67 173.44,62.91 R121.2
  BOTTOM w0.305: 163.56,66.79 163.56,64.3 162.9,63.64 162.9,59.46 161.82,58.38 161.21,58.38 160.53,57.7 160.53,56.12 161.27,55.38 161.27,48.85 160.33,47.91 158.86,47.91 R771.2
  BOTTOM w1.016: 154.97,62 159.76,66.79 163.56,66.79 163.94,67.18 169.43,67.18 R128.2
  vias: v1(151.29,57.09) v1(151.8,57.62)
+V1P8A_SIP: length 88.3
  TOP w0.203: U1.AA1 185.32,66.65 v2(185.31,66.63)
  TOP w0.254: U1.AF16 v2(194.97,64.89) ; C231.2 185.13,66.81 v2(185.31,66.63)
  LAY3 w0.254: v2(172.28,66.86) 172.4,66.75 181.61,66.75 182.37,65.98 188.24,65.98 188.7,66.44 193.54,66.44 194.97,65.01 v2(194.97,64.89)
  LAY3 w0.406: v2(182.37,37.52) 178.75,37.52 v2(178.1,36.86)
  BOTTOM w0.254: v2(185.31,66.63) 184.82,66.14 182.57,66.14 181.94,66.77 177.72,66.77 177,66.04 173.1,66.04 v2(172.28,66.86)
  BOTTOM w0.305: 176.13,41.46 176.13,41.32 176.18,41.27 176.18,38.78 v2(178.1,36.86)
  BOTTOM w0.406: v2(172.28,66.86) 171.97,66.55 R128.1 ; 176.13,41.46 174.62,42.97 174.62,44.27 167.58,51.3 167.58,52.66 164.9,55.34 164.9,62.82 167.23,65.15 R120.2 ; R126.2 183.3,36.59 v2(182.37,37.52)
  BOTTOM w0.635: R128.1 171.56,65.95 R120.2
+V1P8S: length 224.6
  TOP w0.203: R106.1 R107.1 v2(171.44,60.56)
  TOP w0.508: v2(37.7,59.76) 34.51,56.57 34.51,47.38 22.87,35.74 22.87,31.49 v2(22.17,30.79) 21.87,30.49 13.61,30.49 v2(10.56,27.44)
  LAY3 w0.203: v2(171.44,60.56) 171.76,60.56 174.22,63.03 179.88,63.03 180.74,63.89 v2(180.74,63.97)
  LAY6 w0.203: v2(171.44,60.56) 171.44,60.32 170.9,59.77 168.61,59.77 167.39,60.99 162.01,60.99 v2(161.27,60.26)
  LAY6 w0.508: v2(37.7,59.76) 39.74,61.81 40.24,61.81 42.59,64.16 43.4,64.16 44.33,63.23 47.58,63.23 48.76,62.05 63.57,62.05 64.99,60.63 69.25,60.63 69.49,60.87 96.06,60.87 96.75,60.17 101.88,60.17 103.02,59.04 115.14,59.04 118.79,55.39 119.91,55.39 120.6,54.69 123.63,54.69 124.08,55.15 146.96,55.15 147.36,54.75 154.53,54.75 156.98,57.2 158.13,57.2 158.45,56.88 v2(158.45,56.51) ; v2(22.17,30.79) 22.17,26.2 22.61,25.76 22.61,19.2 21.81,18.4 21.81,15.42 v2(21.02,14.63)
  BOTTOM w0.305: R99.1 R98.1 180.76,63.95 v2(180.74,63.97)
  BOTTOM w0.406: FB12.2 10.55,27.43 v2(10.56,27.44) ; R831.2 v2(21.02,14.63)
  BOTTOM w0.508: v2(158.45,56.51) 158.86,56.51 159.4,57.05 159.4,58.75 160.36,59.71
+V3.3_LAN: length 80.8
  TOP w0.305: v2(134.93,43.51) 134.93,40.1 v2(134.82,39.99)
  TOP w0.406: v1(133.85,34.64) 133.85,39.02 v2(134.82,39.99)
  TOP w1.016: v1(119.35,46.36) 119.35,44.19 120.97,42.57 120.97,36.33 v2(120.69,36.05)
  LAY3 w0.305: v2(129.77,42.75) 129.77,41.95 130.74,40.98 133.83,40.98 v2(134.82,39.99)
  LAY6 w1.016: v1(133.85,34.64) 133.39,35.1 v2(128.77,35.1) 126.69,35.1 v2(125.95,35.83) 125.74,36.05 v2(120.69,36.05)
  BOTTOM w0.203: U9.34 130.29,39.1 131.34,38.05 C378.1 131.18,37.72 130.76,37.72 129.78,38.7 U9.35 ; 122.46,43.42 122.9,42.98 U9.12 ; C377.1 130.15,43.12 v2(129.77,42.75) 129.77,42.63 129.03,41.9 U9.27 ; U9.47 124,37.22 123.43,36.65 C381.1 ; U9.39 127.2,36.57 126.92,36.29 126.92,35.74 R328.1 ; U9.42 126,35.88 v2(125.95,35.83) ; U10.5 134.96,43.54 v2(134.93,43.51) ; U9.48 121.99,37.6 C384.1
  BOTTOM w0.305: v2(120.69,36.05) 120.75,35.99 121.19,35.99 C381.1 121.84,36.66 C384.1 ; 122.46,43.42 121.17,44.71 121.15,44.71 119.5,46.36 v1(119.35,46.36) ; R328.1 127.65,34.15 C380.1 ; v2(125.95,35.83) 125.41,35.29 C379.1 ; C382.1 119.6,47.42 R326.1 121.99,47.42 R325.1 122.76,47.41 R321.2
  BOTTOM w0.406: R328.1 127.75,35.1 v2(128.77,35.1)
  BOTTOM w0.508: 134.8,40 v2(134.82,39.99) ; 134.8,40 134.82,40 135.49,39.33 135.49,38.43 134.64,37.57 C383.2 132.53,37.88 C378.1 ; 134.8,40 R311.1
+V3.3_WIFI: length 7
  BOTTOM w0.203: 134.43,31.96 134.43,30.27 135.02,29.69 136.26,29.69 138.06,27.9 U18.5
  vias: v1(134.71,32.1)
+V3.3A_KBC: length 121.7
  TOP w0.203: R408.2 60.42,63.46 R428.2 ; C486.1 47.01,61.18 R427.2
  TOP w0.305: v2(63.84,70.8) 62.46,69.43 v2(60.22,69.43) ; v2(53.04,58.56) 57.64,58.56 59.48,60.4 v2(60.32,60.4) 60.32,63.36 R428.2
  TOP w0.508: U24.8 49.72,60.9 47.08,60.9 C486.1 47.01,60.25 45.5,58.74 v1(42.05,58.74)
  LAY3 w0.203: v2(55.14,75.24) 56.21,75.24 v2(56.24,75.27)
  LAY3 w0.305: v2(43.1,69.43) 43.1,70.69 v2(43.08,70.71)
  LAY3 w0.762: v1(42.05,58.74) 41.32,59.48 41.32,68.36 42.39,69.43 v2(43.1,69.43)
  LAY6 w0.305: v2(53.04,58.56) 49.47,58.56 48.46,59.57
  LAY6 w0.406: v2(57.37,69.46) 60.18,69.46 v2(60.22,69.43)
  LAY6 w0.508: 48.46,59.57 48.45,59.57 46.74,59.57 45.91,58.74 v1(42.05,58.74) ; v2(57.37,69.46) 57.36,69.45 54.78,69.45 v2(54.77,69.44) 54.37,69.83 43.5,69.83 v2(43.1,69.43)
  BOTTOM w0.203: R422.1 50.45,75.39 ; 50.45,75.39 51.19,76.13 52.4,76.13 52.78,75.75 R388.1 R393.1 53.55,75.39 53.89,75.74 54.65,75.74 v2(55.14,75.24) R384.1 ; 50.45,75.39 49.85,75.99 46.91,75.99 46.3,75.39 ; R506.2 56.24,75.82 v2(56.24,75.27) R387.1 ; R420.1 46.3,75.39 ; 46.3,75.39 44.89,75.39 43.08,73.58 v2(43.08,70.71) R380.1 ; v2(60.32,60.4) 61,60.4 61.13,60.26 U22.26 ; R406.2 R405.1 ; v2(54.77,69.44) 54.72,69.48 U22.114 ; v2(43.1,69.43) R379.1 44.27,68.88 45.54,68.88 45.76,68.66 U22.92 ; v2(60.22,69.43) 59.92,69.72 U22.127 ; v2(57.37,69.46) 57.37,70.79 57.52,70.94 U22.121 ; R407.1 42.3,61.13 41.67,60.5 41.44,60.5 ; v2(53.04,58.56) 53.52,58.07 U22.50
  BOTTOM w0.254: v1(42.05,58.74) R406.2
  BOTTOM w0.305: v2(63.84,70.8) 63.83,70.8 R381.1
  BOTTOM w0.406: 41.44,60.5 39.98,60.5 39.52,60.04 FB16.1
  BOTTOM w0.508: FB16.1 39.64,59.59 C479.2
  BOTTOM w0.762: v1(42.05,58.74) 41.5,58.74 40.6,57.84 C479.2 C477.2 R383.2
+V3.3AVCC: length 6.2
  BOTTOM w0.203: U22.74 45.57,61.46
  BOTTOM w0.305: FB16.2 41.52,59.71 42.74,60.93 44.15,60.93 44.68,61.46 ; 44.68,61.46 C480.1 ; 44.68,61.46 45.57,61.46
+V3.3S: length 578.7
  TOP w0.203: v2(186.85,81.39) 187.17,81.39 R15.1 ; v2(196.41,47.43) 196.66,47.43 197.03,47.8 R69.1 ; R382.2 v2(181.21,58.59) 180.32,59.48 179.44,59.48 179.16,59.77 R264.2 ; Q2.1 171.9,73.92 171.49,73.51 R85.2 170.85,72.99 170.64,72.77 170.64,69.88 170.89,69.62 R84.2 171.61,69.82 172.37,70.58 Q3.1 172.96,69.81 173.28,69.49 173.64,69.49 174.15,68.97 176.31,68.97 R109.1 177.04,68.24 R108.1 176.41,67.71 176.26,67.56 R111.1 R110.1 ; U2.5 v2(168.06,49.99) ; v2(131.2,90.14) 131.5,89.84 R3107.1
  TOP w0.254: v2(88.65,33.67) 89.81,33.67 89.99,33.85 R199.1 ; CN16.14 73.38,66.43 v2(73.66,66.71) 73.88,66.49 CN16.15 ; v2(66.64,61.96) 67.4,62.72 67.4,64.03 66.88,64.56 CN16.1 66.88,66.55 67.07,66.75 v2(67.4,66.75) 67.38,66.72 CN16.2 ; v2(75.35,66.65) 75.38,66.62 CN16.18 ; R95.1 172.01,59.17 v2(172.02,59.16) 172.02,59.15 R97.2 ; R180.1 v2(80.09,57.01) ; 173.87,20.48 CN1.255
  TOP w0.305: v2(169.36,19.2) 169.36,12.86 168.34,11.84 168.34,10.12 168.85,9.61 169.97,9.61 170.25,9.89 R491.2 R389.2 ; U27.5 132.34,81.09 C510.2 v2(132.33,80.39) 131.83,79.89 130.62,79.89 130.42,79.69 v1(130.27,79.69) ; R3108.1 132.07,85.81 v2(131.11,86.77) ; R537.1 v2(139.54,57.43) ; Q2.1 172.95,74.41 172.67,74.68 172.67,75.17 173.58,76.08 v2(173.86,76.08) ; R607.1 v2(160.22,19.9)
  TOP w0.508: R818.2 35.93,58.87 35.3,58.24 32.83,58.24 ; v2(167.06,21.5) C249.2 167.06,22.24 C248.2 169.62,22.24 171.72,20.14 173.53,20.14 173.87,20.48 ; v1(104.25,65.24) 113.11,56.37 120.88,56.37 121.6,55.65 126.14,55.65 132.34,49.45 132.34,48.64 133.44,47.53 v2(133.44,44.98)
  TOP w0.762: FB37.1 142.66,84.97 144.23,83.41 144.23,78.47 142.49,76.73 142.49,75.19 143.26,74.42 v2(147.3,74.42)
  TOP w1.016: v2(18.31,33.11) v2(18.31,33.68) 18.31,38.82 28.64,49.16 28.64,55.55
  LAY3 w0.254: v2(88.65,33.67) 88.65,35.71 80.09,44.27 v2(80.09,57.01)
  LAY3 w0.305: v2(132.33,80.39) 132.33,85.56 v2(131.11,86.77) ; v2(186.85,81.39) 177.13,81.39 173.86,78.12 v2(173.86,76.08) ; v2(161.31,68.52) 165.98,63.85 v2(165.98,58.28) 165.51,57.81 165.51,56.23 167.53,54.21 167.53,50.52 v2(168.06,49.99)
  LAY3 w0.508: v2(160.22,19.9) 156.12,19.9 137.13,38.9 137.13,42.5 134.65,44.98 v2(133.44,44.98) ; v2(83.41,99.88) 83.41,77.54 v2(82.15,76.28)
  LAY3 w0.762: v1(130.27,79.69) 135.54,74.42 v2(147.3,74.42)
  LAY4 w0.305: v2(196.41,47.43) 196.21,47.23 191.45,47.23 190.91,47.76 190.91,48.28 190.19,49 185.31,49 184.72,49.59 177.28,49.59 177.12,49.42 175.09,49.42 174.53,49.99 v2(168.06,49.99)
  LAY4 w0.406: v2(166.68,75.37) 166.68,74.96 166.13,74.42 v2(147.3,74.42)
  LAY6 w0.254: v2(73.66,66.71) 73.19,66.24 70.09,66.24 v2(69.58,66.75) ; v2(38.66,63.41) 40.73,65.48 45.38,65.48 46.73,64.12 63.88,64.12 66.05,61.96 v2(66.64,61.96)
  LAY6 w0.508: v2(165.98,58.28) 166.58,58.87 171.73,58.87 v2(172.02,59.16)
  BOTTOM w0.152: v2(133.44,44.98) 133.44,44.98 R315.2
  BOTTOM w0.203: U17.5 17.41,28.62 C459.2 17.84,29.05 R369.1 ; v2(131.2,90.14) 131.11,90.05 v2(131.11,86.77) ; v2(38.66,63.41) C485.2 39.19,63.41 U23.5
  BOTTOM w0.254: v2(67.4,66.75) 67.72,67.06 69.27,67.06 v2(69.58,66.75) ; 18.75,32.96 R369.1 18.75,28.57 18.45,28.27 18.45,26.04 19.11,25.38 19.7,25.38 20.09,25.77 R370.1 ; v2(73.66,66.71) 74.23,66.14 74.84,66.14 v2(75.35,66.65)
  BOTTOM w0.305: v2(75.35,66.65) 76.37,67.66 81.54,67.66 ; v2(181.21,58.59) 180.93,58.59 180.05,59.47 175.25,59.47 174.43,58.64 172.54,58.64 v2(172.02,59.16) ; R371.1 24.09,32.92 22.83,34.18 20.68,34.18 20.21,33.71 ; R271.1 162.86,28.62 160.22,25.98 v2(160.22,19.9) ; v2(173.86,76.08) 173.38,76.56 167.87,76.56 v2(166.68,75.37) 166.68,74.95 166.2,74.47 165.26,74.47 163.85,73.06 163.85,71.06 v2(161.31,68.52) ; R16.1 195.72,48.12 v2(196.41,47.43) ; v2(139.54,57.43) 139.54,66.33 147.3,74.09 v2(147.3,74.42) ; R398.2 67.4,66.74 v2(67.4,66.75) ; 195.99,12 196.12,12.12 R386.2
  BOTTOM w0.406: 6.9,30.04 6.09,30.04 ; 6.9,30.04 8.61,28.33 FB11.2 ; 6.9,30.04 6.9,30.93 ; 6.9,30.04 6.45,30.49
  BOTTOM w0.508: v2(160.22,19.9) 160.56,19.57 162.97,19.57 164.9,21.5 v2(167.06,21.5) 167.06,21.33 169.19,19.2 v2(169.36,19.2) 169.87,18.69 169.87,17.47 175.2,12.14 179.74,12.14 181.22,10.65 194.65,10.65 195.99,12 ; v2(83.41,99.88) 80.87,102.42 FB19.2
  BOTTOM w0.762: FB39.2 147.87,74.99 v2(147.3,74.42)
  vias: v1(32.29,58.28) v1(32.29,57.51) v1(32.29,56.75) v1(32.29,55.99) v1(33.05,58.28) v1(33.05,57.51) v1(33.05,56.75) v1(33.05,55.99) v1(113.23,72.56) v1(114.08,72.54) v1(129.42,79.71)
